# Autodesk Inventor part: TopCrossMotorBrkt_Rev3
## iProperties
Created: 2008-11
Part Number: TopCrossMotorBrkt_Rev3
Document SubType Name: Modeling
Designer: ETUDIANT
Author: ETUDIANT
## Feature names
1. Base1
2. Extrusion1
3. Extrusion2
